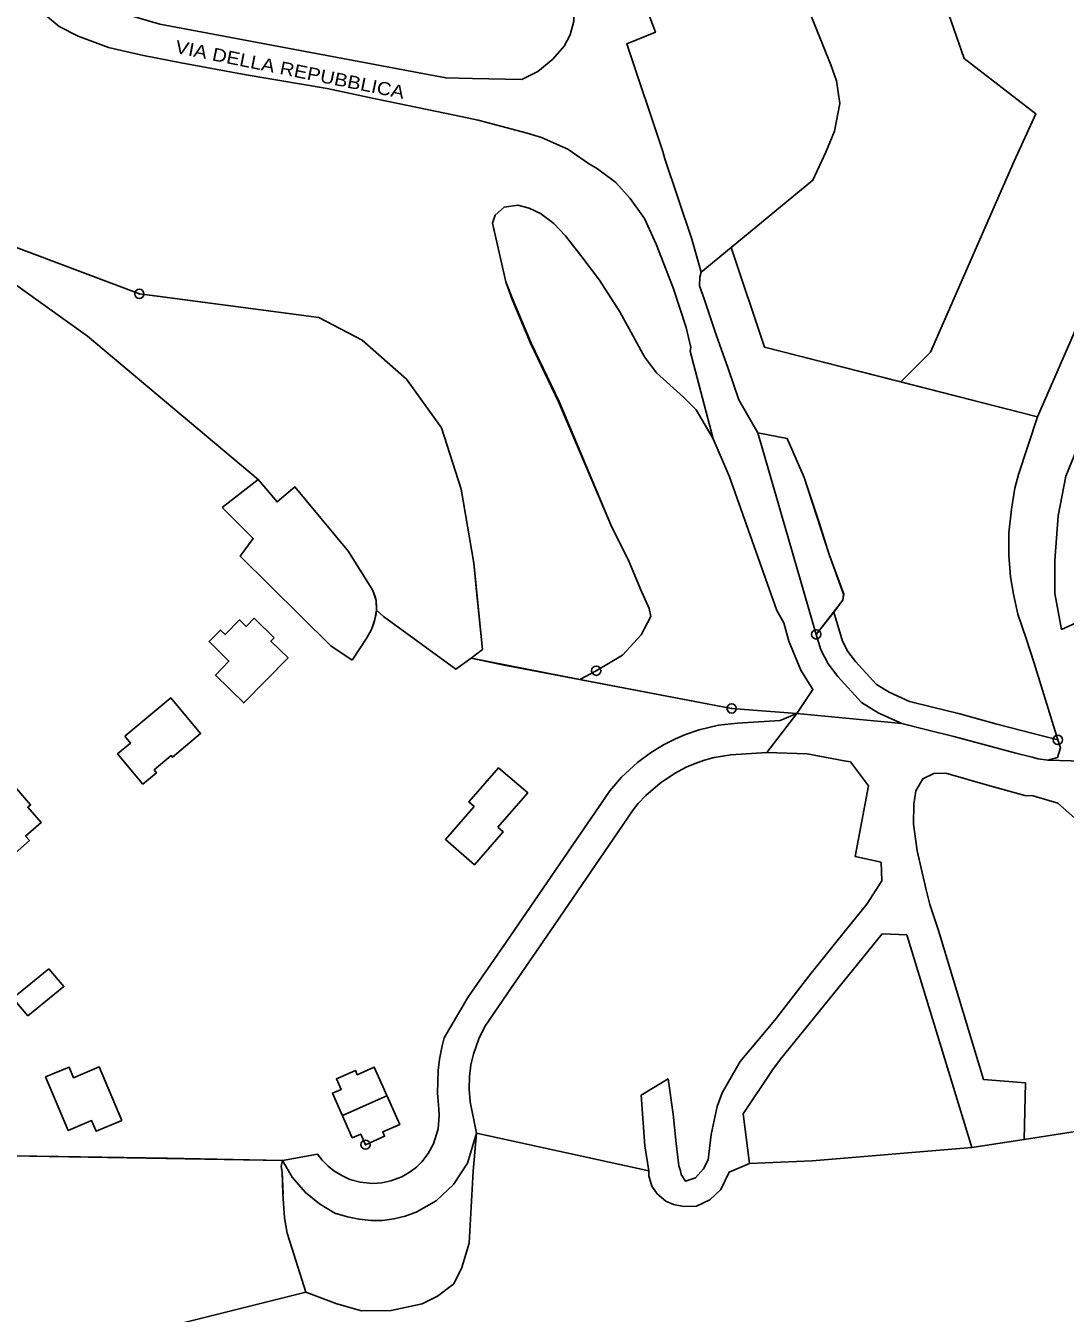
# Model space of a CAD drawing. Extents: x 654952 to 658955, y 890426 to 894481.
# Drawn here: x 657405.1 to 657629.2, y 891411.2 to 891688.7 of the extents above; entities that cross this region are included whole.
import ezdxf

# ---------------------------------------------------------------- set-up
doc = ezdxf.new("R2010")
doc.units = 0
doc.header["$LTSCALE"] = 4
doc.header["$PDMODE"] = 32
doc.header["$PDSIZE"] = 2
for name, color, linetype, lineweight in [('11', 7, 'Continuous', 25), ('14', 7, 'Continuous', 25), ('17', 7, 'Continuous', 25), ('18', 7, 'Continuous', 25), ('19', 7, 'Continuous', 25), ('32', 7, 'Continuous', 25), ('33', 7, 'Continuous', 25), ('5', 7, 'Continuous', 25), ('6', 7, 'Continuous', 25), ('9', 7, 'Continuous', 25)]:
    doc.layers.add(name, color=color, linetype=linetype, lineweight=lineweight)
doc.layers.add('58', color=7, linetype='Continuous')

msp = doc.modelspace()

# ---------------------------------------------------------------- linework, layer by layer
at = {"layer": '11'}
for points in [[(657536.04, 891519.7), (657537.15, 891521.09), (657538.76, 891522.8), (657541.9, 891525.5), (657544.99, 891527.57), (657547.51, 891528.89), (657549.45, 891529.72), (657551.45, 891530.43), (657553.5, 891531), (657557.09, 891531.61), (657564.89, 891532.09), (657573.54, 891531.8), (657581.52, 891530.26), (657582.89, 891530.1), (657586.75, 891524.92), (657583.92, 891509.65), (657589.53, 891508.48)], [(657612.44, 891525.06), (657603.45, 891527.64), (657600.85, 891527.58), (657598.53, 891526.44), (657597.01, 891523.81), (657596.57, 891520.94), (657596.5, 891516.66), (657597.25, 891510.92), (657599.18, 891502.46), (657600, 891499.29), (657601.87, 891493.71), (657611.58, 891461.59), (657620.6, 891460.91), (657620.37, 891448.67), (657651.61, 891453.59), (657647.29, 891466.67), (657646.69, 891468.3), (657639.1, 891492.2), (657638.77, 891494.29)], [(657638.77, 891494.29), (657635.87, 891502.88), (657631.27, 891517.96), (657627.62, 891521.13), (657622.31, 891522.75), (657620.45, 891522.84), (657612.44, 891525.06)], [(657502.32, 891450.02), (657500.91, 891456.77), (657500.69, 891459.53), (657500.77, 891462.22), (657501.09, 891464.75), (657501.61, 891467.08), (657502.76, 891470.34), (657504.09, 891473.02), (657509.87, 891481.47), (657518.23, 891493.68), (657532.81, 891514.99), (657536.04, 891519.7)], [(657589.53, 891508.48), (657589.69, 891504.43), (657586.45, 891499.36), (657581.8, 891493.72), (657574.45, 891484.53), (657566.61, 891474.36), (657559.15, 891465.47), (657555.22, 891458.75), (657554.15, 891455.81), (657552.85, 891449.75), (657552.25, 891444.26), (657551.19, 891442.34), (657549.5, 891440.43), (657547.35, 891439.69), (657546.44, 891441.15), (657546.23, 891441.94), (657545.89, 891443.03), (657545.32, 891447.82), (657544.66, 891454.16), (657543.59, 891461.72), (657537.79, 891458.26), (657538.56, 891447.28), (657539.42, 891441.94), (657502.32, 891450.02)]]:
    msp.add_lwpolyline(points, dxfattribs=at)
msp.add_lwpolyline([(657567.81, 891465.96), (657589.76, 891493), (657595.02, 891492.76), (657609.06, 891446.97), (657574.67, 891444.05), (657561.12, 891443.52), (657559.77, 891454.2), (657566.15, 891463.76)], close=True, dxfattribs=at)
at = {"layer": '14'}
for points in [[(657571.63, 891697.78), (657578.7, 891680.26), (657579.86, 891676.86), (657580.58, 891671.95), (657579.45, 891666.01), (657577.58, 891661.44), (657574.82, 891655.41), (657557.15, 891640.89), (657564.35, 891619.47), (657593.79, 891611.94), (657600.13, 891618.34), (657618.17, 891659.54), (657622.86, 891669.7), (657607.43, 891681.63), (657589.08, 891734.34)], [(657557.28, 891541.57), (657524.55, 891547.8), (657528.1, 891549.71), (657533.76, 891553.06), (657537.8, 891557.41), (657539.84, 891561.4), (657539.53, 891563.14), (657537.66, 891567.25), (657534.97, 891573.65), (657531.49, 891580.63), (657519.98, 891607.69), (657513.95, 891620.31), (657510.01, 891629.68), (657508.61, 891633.49), (657505.74, 891646.17), (657506.32, 891647.92), (657508.22, 891649.62), (657511.18, 891650.01), (657513.67, 891649.41), (657516.12, 891648.27), (657518.95, 891646.06), (657521.49, 891643.41), (657524.99, 891638.94), (657528.77, 891633.84), (657533.18, 891627.04), (657538.49, 891617.32), (657541.06, 891613.9)], [(657541.06, 891613.9), (657546.91, 891608.63), (657549.64, 891605.93), (657553.31, 891599.66), (657556.8, 891591.46), (657567.02, 891562.66)], [(657567.02, 891562.66), (657568.57, 891560.05), (657569.63, 891556.08), (657572.23, 891549.79), (657574.79, 891545.67), (657571.32, 891540.46), (657557.28, 891541.57)]]:
    msp.add_lwpolyline(points, dxfattribs=at)
msp.add_point((657557.28, 891541.57), dxfattribs=at)
at = {"layer": '17'}
for points in [[(657651.61, 891453.59), (657620.37, 891448.67), (657609.06, 891446.97), (657574.67, 891444.05), (657561.12, 891443.52), (657556.76, 891441.67), (657554.92, 891437.87), (657552.58, 891435.65), (657549.7, 891434.31), (657546.97, 891434.25), (657544.74, 891434.69), (657543.13, 891435.39), (657541.21, 891436.96), (657540.11, 891438.59), (657539.43, 891440.88), (657539.42, 891441.94), (657502.32, 891450.02)], [(657502.32, 891450.02), (657501.58, 891441.87), (657500.7, 891426.32), (657499.1, 891421.08), (657497.41, 891417.57), (657493.9, 891414.91), (657490.61, 891413.25), (657483.89, 891411.8), (657477.48, 891411.73), (657472.18, 891413.29), (657465.47, 891415.8), (657379.19, 891394.2)], [(657472.18, 891413.29), (657477.48, 891411.73), (657483.89, 891411.8), (657490.61, 891413.25), (657493.9, 891414.91), (657497.41, 891417.57), (657499.1, 891421.08), (657500.7, 891426.32), (657501.58, 891441.87), (657502.32, 891450.02), (657500.34, 891443.59), (657497.35, 891438.99)], [(657471.75, 891432.78), (657468.43, 891434.83), (657465.43, 891437.22), (657462.57, 891440.53), (657460.49, 891444.17), (657460.21, 891442.85), (657460.39, 891441.67), (657460.59, 891437)], [(657497.35, 891438.99), (657493.63, 891435.44), (657489.29, 891433), (657486.95, 891432.14), (657484.5, 891431.55), (657482.05, 891431.25), (657479.55, 891431.22), (657476.99, 891431.48), (657474.51, 891432.04), (657471.75, 891432.78)], [(657460.58, 891437), (657460.88, 891431.76), (657461.51, 891428.49), (657462.51, 891425.34), (657465.47, 891415.8), (657472.18, 891413.29)]]:
    msp.add_lwpolyline(points, dxfattribs=at)
at = {"layer": '18'}
for points in [[(657575.52, 891557.54), (657581.28, 891564.88), (657581.44, 891566.22), (657578.28, 891574.76), (657576.12, 891581.63), (657572.92, 891591.37), (657569.26, 891599.75), (657562.94, 891600.94)], [(657410.14, 891485.45), (657402.37, 891479.15), (657405.6, 891475.33), (657413.37, 891481.63)]]:
    msp.add_lwpolyline(points, close=True, dxfattribs=at)
for points in [[(657474.7, 891575.38), (657463.15, 891589.31), (657459.31, 891586.11), (657455.2, 891590.93), (657447.48, 891584.85)], [(657447.48, 891584.85), (657454.18, 891578.21), (657451.35, 891574.36), (657470.88, 891555.09), (657475.47, 891552.01)], [(657475.47, 891552.01), (657478.66, 891556.78), (657479.64, 891558.61), (657480.41, 891560.73), (657480.75, 891562.79), (657480.66, 891564.82), (657479.94, 891566.96), (657474.7, 891575.38)]]:
    msp.add_lwpolyline(points, dxfattribs=at)
msp.add_point((657575.52, 891557.54), dxfattribs=at)
at = {"layer": '19'}
for points in [[(657627.6, 891534.79), (657628.17, 891533.07), (657627.52, 891531), (657625.45, 891530.42), (657623.33, 891530.7), (657622.04, 891531.05), (657618.56, 891531.96), (657613.2, 891533.35), (657605.18, 891535.54), (657599.1, 891537.05), (657593.99, 891538.35), (657588.86, 891540.64), (657585.28, 891542.87), (657580.15, 891548.47), (657578.1, 891551.16), (657576.5, 891554.19), (657575.51, 891557.54), (657579.3, 891562.36)], [(657579.3, 891562.36), (657581.15, 891556.08), (657582.33, 891553.86), (657583.99, 891551.68), (657588.5, 891546.75), (657591.21, 891545.07), (657595.64, 891543.09), (657600.32, 891541.9), (657606.44, 891540.38), (657614.48, 891538.18), (657627.6, 891534.79)]]:
    msp.add_lwpolyline(points, dxfattribs=at)
msp.add_point((657627.6, 891534.79), dxfattribs=at)
at = {"layer": '32'}
msp.add_lwpolyline([(657379.19, 891394.2), (657465.47, 891415.8), (657462.51, 891425.34), (657461.51, 891428.49), (657460.88, 891431.76), (657460.58, 891437), (657460.39, 891441.67), (657460.21, 891442.85), (657460.49, 891444.17), (657393.37, 891445.28)], dxfattribs=at)
at = {"layer": '33'}
msp.add_line((657500.41, 891479.3), (657495.33, 891470.58), dxfattribs=at)
for points in [[(657435.67, 891444.62), (657393.37, 891445.28), (657394.07, 891435.22), (657386.64, 891435.1), (657369.3, 891520.67), (657309.08, 891592.79), (657241.81, 891673.31)], [(657400.23, 891642.01), (657429.62, 891630.91), (657468.34, 891625.81), (657477.62, 891620.95), (657487.17, 891612.52), (657494.75, 891602.06), (657498.97, 891588.85), (657501.72, 891572.87), (657503.56, 891554.3), (657501.11, 891552.38), (657497.87, 891550.01), (657482.22, 891561.42), (657480.75, 891562.79), (657480.77, 891563.22), (657480.67, 891564.82), (657480.48, 891565.65), (657479.95, 891566.96), (657474.7, 891575.38), (657463.15, 891589.31), (657459.31, 891586.1), (657455.2, 891590.93), (657418.41, 891621.84), (657394.81, 891638.71)], [(657394.8, 891638.71), (657418.41, 891621.84), (657455.2, 891590.93), (657447.48, 891584.85)], [(657447.48, 891584.85), (657454.18, 891578.21), (657451.35, 891574.36), (657470.88, 891555.09), (657475.47, 891552.01)], [(657475.47, 891552.01), (657478.66, 891556.78), (657479.64, 891558.61), (657480.1, 891559.73), (657480.41, 891560.73), (657480.65, 891561.88), (657480.75, 891562.79), (657482.21, 891561.42)], [(657482.21, 891561.42), (657497.87, 891550.01), (657501.11, 891552.39), (657507.92, 891550.96), (657557.28, 891541.57), (657571.32, 891540.46), (657567.75, 891538.97), (657558.52, 891538.43), (657554.45, 891537.94), (657550.29, 891536.98), (657547.37, 891535.96), (657545.17, 891535.03), (657542.63, 891533.75), (657539.8, 891532.02), (657537.02, 891529.96), (657533.53, 891526.74), (657531, 891523.8), (657527.93, 891519.3)], [(657571.32, 891540.46), (657567.75, 891538.97), (657558.52, 891538.43), (657554.45, 891537.94), (657550.29, 891536.98), (657547.37, 891535.96), (657545.17, 891535.03), (657542.63, 891533.75), (657539.8, 891532.02), (657537.02, 891529.96), (657533.53, 891526.74), (657531, 891523.8), (657527.93, 891519.3)], [(657551.45, 891530.43), (657553.5, 891531), (657557.09, 891531.61), (657564.89, 891532.09), (657571.32, 891540.46)], [(657536.04, 891519.7), (657537.15, 891521.09), (657538.76, 891522.8), (657541.9, 891525.5), (657544.99, 891527.57), (657547.51, 891528.89), (657549.45, 891529.72), (657551.45, 891530.43)], [(657527.93, 891519.3), (657522.92, 891511.95), (657515.7, 891501.47), (657508.67, 891491.24), (657500.41, 891479.3), (657495.33, 891470.58)], [(657527.93, 891519.3), (657522.92, 891511.95), (657515.7, 891501.47), (657508.67, 891491.24), (657500.41, 891479.3)], [(657502.32, 891450.02), (657500.91, 891456.77), (657500.69, 891459.53), (657500.77, 891462.22), (657501.09, 891464.75), (657501.61, 891467.08), (657502.76, 891470.34), (657504.09, 891473.02), (657509.87, 891481.47), (657518.23, 891493.68), (657532.81, 891514.99), (657536.04, 891519.7)], [(657495.33, 891470.58), (657494.89, 891468.89), (657494.32, 891465.96), (657494.01, 891463.53), (657493.88, 891458.65), (657494.16, 891455.21), (657494.26, 891453.87), (657494.04, 891451.01), (657493.05, 891447.75), (657491.9, 891445.64), (657490.54, 891443.88), (657489.33, 891442.7), (657488.01, 891441.68), (657486.22, 891440.64), (657483.85, 891439.74), (657481.85, 891439.32), (657479.87, 891439.19), (657477.23, 891439.45), (657475.01, 891440.07), (657473.24, 891440.91)], [(657495.33, 891470.58), (657494.89, 891468.89), (657494.32, 891465.96), (657494.01, 891463.53), (657493.88, 891458.65), (657494.16, 891455.21), (657494.26, 891453.87), (657494.04, 891451.01), (657493.05, 891447.75), (657491.9, 891445.64), (657490.54, 891443.88), (657489.33, 891442.7), (657488.01, 891441.68), (657486.22, 891440.64), (657483.85, 891439.74), (657481.85, 891439.32), (657479.87, 891439.19), (657477.23, 891439.45), (657475.01, 891440.07), (657473.24, 891440.91)], [(657465.43, 891437.22), (657468.43, 891434.83), (657471.75, 891432.78), (657474.51, 891432.04), (657476.99, 891431.48), (657479.55, 891431.22), (657482.05, 891431.25), (657484.5, 891431.55), (657486.95, 891432.14), (657489.29, 891433), (657493.63, 891435.44), (657497.35, 891438.99), (657500.34, 891443.59), (657502.32, 891450.02)], [(657473.24, 891440.91), (657471.51, 891441.93), (657470.31, 891442.91), (657469.03, 891444.24), (657468.04, 891445.54), (657460.49, 891444.17), (657435.67, 891444.62)], [(657473.24, 891440.91), (657471.51, 891441.93), (657470.31, 891442.91), (657469.03, 891444.24), (657468.04, 891445.54), (657460.49, 891444.17), (657462.57, 891440.53), (657465.43, 891437.22)]]:
    msp.add_lwpolyline(points, dxfattribs=at)
at = {"layer": '5'}
for p, q in [((657575.52, 891557.54), (657562.94, 891600.94)), ((657571.32, 891540.46), (657593.99, 891538.35))]:
    msp.add_line(p, q, dxfattribs=at)
for points in [[(657493.05, 891718.92), (657495.32, 891719.49), (657496.49, 891719.4), (657505.82, 891717.61), (657509.57, 891716.5), (657512.54, 891714.77), (657515.53, 891712.53), (657518.22, 891709.64), (657520.12, 891706.27), (657521.62, 891702.13), (657522.77, 891697.46), (657523.2, 891694.06), (657523.25, 891689.69), (657522.48, 891686.72), (657521.17, 891684.28), (657518.74, 891681.53), (657515.54, 891678.84), (657512.03, 891677.11), (657501.45, 891677.37), (657495.69, 891677.51), (657434, 891689.06), (657424.67, 891691.78)], [(657562.94, 891600.94), (657558.81, 891608.09), (657556.51, 891614.85), (657553.98, 891622.1), (657551.38, 891629.84), (657550.35, 891632.65), (657550.4, 891634.52), (657550.74, 891635.6), (657548.69, 891642.72), (657542.89, 891660), (657542.44, 891661.57), (657534.68, 891684.82), (657540.84, 891687.29), (657531.06, 891713.58), (657529.05, 891712.8), (657527.09, 891711.76)], [(657405.83, 891693.98), (657412.36, 891688.52), (657416.42, 891686.48), (657420.67, 891684.85), (657422.95, 891684.04), (657426.72, 891683.18), (657430.49, 891682.32), (657438.63, 891680.71)], [(657658.46, 891692.53), (657658.79, 891689.12), (657657.69, 891683.67), (657656.58, 891678.97), (657655.66, 891675.31), (657653.6, 891669.86), (657650.32, 891662.32), (657648.79, 891661.73), (657644.82, 891652.84), (657634.79, 891630.7), (657632.64, 891625.95), (657623.23, 891604.4), (657619.09, 891592)], [(657438.63, 891680.71), (657452.65, 891678.12), (657470.09, 891675.16), (657479.12, 891673.26), (657497.53, 891669.47), (657502.67, 891668.35), (657507.54, 891667.04), (657513.19, 891665.59), (657516.32, 891664.61), (657521.95, 891662.11), (657526.46, 891659)], [(657526.46, 891659), (657528.37, 891657.87), (657532.3, 891654.92), (657535.38, 891651.46), (657538.48, 891647.19), (657541.03, 891641.6), (657544.68, 891632.2), (657547.46, 891623.7), (657548.49, 891619.33), (657548.37, 891618.6), (657553.31, 891599.66), (657556.8, 891591.46), (657567.02, 891562.66)], [(657627.6, 891534.79), (657628.17, 891533.07), (657627.52, 891531), (657625.45, 891530.42), (657645.47, 891529.84), (657645.56, 891536.63), (657633.9, 891561.11), (657628.36, 891558.61), (657626.93, 891566.36), (657626.93, 891573.49), (657627.68, 891583.11), (657629.3, 891591.67), (657631.12, 891596.05), (657640, 891619.78), (657641.69, 891619.02), (657654.9, 891646.35)], [(657619.09, 891592), (657618.35, 891589.03), (657617.59, 891584.52), (657617.04, 891579.4), (657617, 891574.63), (657617.36, 891569.93), (657618.03, 891566.21), (657618.95, 891561.92), (657620.74, 891556.63), (657622.5, 891551.32), (657627.6, 891534.79)], [(657567.02, 891562.66), (657568.57, 891560.05), (657569.63, 891556.08), (657572.23, 891549.79), (657574.79, 891545.67), (657571.32, 891540.46), (657593.99, 891538.35)], [(657593.99, 891538.35), (657588.86, 891540.64), (657585.28, 891542.87), (657580.15, 891548.47), (657578.1, 891551.16), (657576.5, 891554.19), (657575.51, 891557.54)], [(657625.45, 891530.42), (657623.33, 891530.7), (657622.04, 891531.05), (657618.56, 891531.96), (657613.2, 891533.35), (657605.18, 891535.54), (657599.1, 891537.05), (657593.99, 891538.35), (657571.32, 891540.46), (657564.89, 891532.09)], [(657564.89, 891532.09), (657573.54, 891531.8), (657581.52, 891530.26), (657582.89, 891530.1), (657586.75, 891524.92), (657583.92, 891509.65), (657589.53, 891508.48)], [(657658, 891467.15), (657647.42, 891500.81), (657640.71, 891522.01), (657645.47, 891529.84), (657625.45, 891530.42)], [(657600, 891499.29), (657599.18, 891502.46), (657597.25, 891510.92), (657596.5, 891516.66), (657596.57, 891520.94), (657597.01, 891523.81), (657598.53, 891526.44), (657600.85, 891527.58), (657603.45, 891527.64), (657612.44, 891525.06), (657620.45, 891522.84)], [(657620.45, 891522.84), (657622.31, 891522.75), (657627.62, 891521.13), (657631.27, 891517.96), (657635.87, 891502.88), (657638.77, 891494.29), (657639.1, 891492.2), (657646.69, 891468.3), (657647.29, 891466.67), (657651.61, 891453.59), (657654.91, 891446.58)], [(657589.53, 891508.48), (657589.69, 891504.43), (657586.45, 891499.36), (657581.8, 891493.72), (657574.45, 891484.53), (657566.61, 891474.36), (657559.15, 891465.47), (657555.22, 891458.75), (657554.15, 891455.81), (657552.85, 891449.75), (657552.25, 891444.26), (657551.19, 891442.34), (657549.5, 891440.43), (657547.35, 891439.69), (657546.44, 891441.15), (657546.23, 891441.94), (657545.89, 891443.03), (657545.32, 891447.82), (657544.66, 891454.16), (657543.59, 891461.72), (657537.79, 891458.26), (657538.56, 891447.28), (657539.42, 891441.94), (657539.43, 891440.88), (657540.11, 891438.59), (657541.21, 891436.96), (657543.13, 891435.39), (657544.74, 891434.69), (657546.97, 891434.25), (657549.7, 891434.31), (657552.58, 891435.65), (657554.92, 891437.87), (657556.76, 891441.67), (657561.12, 891443.52), (657559.77, 891454.2), (657566.15, 891463.76), (657567.81, 891465.96), (657589.76, 891493), (657595.02, 891492.76), (657609.06, 891446.97)], [(657609.06, 891446.97), (657620.37, 891448.67), (657620.6, 891460.91), (657611.58, 891461.59), (657601.87, 891493.71), (657600, 891499.29)]]:
    msp.add_lwpolyline(points, dxfattribs=at)
at = {"layer": '6'}
msp.add_line((657473.39, 891453.84), (657482.99, 891458.1), dxfattribs=at)
for points in [[(657458.65, 891556.81), (657454.37, 891561.02), (657452.62, 891559.23), (657451.2, 891560.64), (657448.11, 891557.5), (657447.11, 891558.48), (657444.66, 891555.98), (657448.94, 891551.78), (657446, 891548.78), (657452.13, 891542.75), (657461.66, 891552.45), (657457.95, 891556.1)], [(657426.49, 891535.57), (657436.39, 891543.84), (657442.8, 891536.16), (657436.73, 891531.1), (657436.48, 891531.41), (657432.79, 891528.33), (657433.3, 891527.72), (657430.38, 891525.28), (657424.94, 891531.81), (657427.7, 891534.11)], [(657409.4, 891462.15), (657414.26, 891450.63), (657419.33, 891452.77), (657420.3, 891450.47), (657425.83, 891452.8), (657420.97, 891464.32), (657415.44, 891461.98), (657414.47, 891464.29)], [(657478.36, 891447.56), (657477.35, 891449.85), (657475.52, 891449.04), (657471.26, 891458.64), (657473.09, 891459.45), (657472.08, 891461.73), (657476.19, 891463.56), (657476.6, 891462.64), (657480.25, 891464.27), (657485.73, 891451.93), (657482.07, 891450.3), (657482.48, 891449.39)]]:
    msp.add_lwpolyline(points, close=True, dxfattribs=at)
for points in [[(657501.76, 891520.44), (657500.63, 891521.42), (657507.06, 891528.81), (657513.32, 891523.36), (657506.89, 891515.97)], [(657405.96, 891513.08), (657405.09, 891514.08), (657408.42, 891516.96), (657405.56, 891520.27), (657406.16, 891520.79), (657402.24, 891525.33)], [(657506.89, 891515.97), (657508.02, 891514.99), (657501.84, 891507.9), (657495.58, 891513.35), (657501.76, 891520.44)], [(657392.19, 891517.68), (657397.16, 891511.94), (657397.76, 891512.46), (657400.97, 891508.76), (657405.96, 891513.08)]]:
    msp.add_lwpolyline(points, dxfattribs=at)
msp.add_point((657478.36, 891447.56), dxfattribs=at)
at = {"layer": '9'}
msp.add_line((657528.1, 891549.71), (657524.55, 891547.8), dxfattribs=at)
for points in [[(657578.61, 891784.11), (657582.17, 891781.28), (657584.94, 891779.5), (657587.7, 891777.72), (657597.04, 891775.75), (657593.2, 891771.15), (657589.35, 891766.55), (657583.84, 891761.75), (657581.13, 891753.01), (657589.08, 891734.34), (657607.43, 891681.63), (657622.86, 891669.7), (657618.17, 891659.54), (657600.13, 891618.34), (657593.79, 891611.94), (657623.23, 891604.4)], [(657409.21, 891719.99), (657408.32, 891715.99), (657408.22, 891712.03), (657408.92, 891708.47), (657410.21, 891704.31), (657411.99, 891701.34), (657414.04, 891698.48), (657416.55, 891696.07), (657420.03, 891693.69), (657422.69, 891692.44), (657424.67, 891691.78), (657434, 891689.06), (657495.69, 891677.51), (657501.45, 891677.37)], [(657501.45, 891677.37), (657512.03, 891677.11), (657515.54, 891678.84), (657518.74, 891681.53), (657521.17, 891684.28), (657522.48, 891686.72), (657523.25, 891689.69), (657523.2, 891694.06), (657522.77, 891697.46), (657521.62, 891702.13), (657520.12, 891706.27), (657518.22, 891709.64), (657515.53, 891712.53), (657512.54, 891714.77), (657509.57, 891716.5), (657505.82, 891717.61), (657496.49, 891719.4), (657495.32, 891719.49), (657493.05, 891718.92)], [(657405.83, 891693.98), (657412.36, 891688.52), (657416.42, 891686.48), (657420.67, 891684.85), (657422.95, 891684.04), (657426.72, 891683.18), (657430.49, 891682.32), (657438.63, 891680.71), (657452.65, 891678.12), (657470.09, 891675.16), (657479.12, 891673.26)], [(657429.62, 891630.91), (657400.23, 891642.01), (657363.97, 891674.93)], [(657479.12, 891673.26), (657497.53, 891669.47), (657502.67, 891668.35), (657507.54, 891667.04), (657513.19, 891665.59), (657516.32, 891664.61), (657521.95, 891662.11), (657526.46, 891659)], [(657623.23, 891604.4), (657632.64, 891625.95), (657634.79, 891630.7), (657644.82, 891652.84), (657648.79, 891661.73)], [(657526.46, 891659), (657528.37, 891657.87), (657532.3, 891654.92), (657535.38, 891651.46), (657538.48, 891647.19), (657541.03, 891641.6), (657544.68, 891632.2), (657547.46, 891623.7), (657548.49, 891619.33), (657548.37, 891618.6), (657553.31, 891599.66), (657549.64, 891605.93), (657546.91, 891608.63), (657541.06, 891613.9), (657538.49, 891617.32), (657533.18, 891627.04), (657528.77, 891633.84), (657524.99, 891638.94), (657521.49, 891643.41), (657518.95, 891646.06), (657516.12, 891648.27), (657513.67, 891649.41), (657511.18, 891650.01), (657508.22, 891649.62), (657506.32, 891647.92), (657505.74, 891646.17), (657508.61, 891633.49), (657510.13, 891629.69), (657514.07, 891620.32), (657520.1, 891607.7), (657531.49, 891580.63), (657534.97, 891573.65), (657537.66, 891567.25), (657539.53, 891563.14), (657539.84, 891561.4), (657537.8, 891557.41), (657533.76, 891553.06), (657528.1, 891549.71)], [(657562.94, 891600.94), (657558.81, 891608.09), (657556.51, 891614.85), (657553.98, 891622.1), (657551.38, 891629.84), (657550.35, 891632.65), (657550.4, 891634.52), (657550.74, 891635.6), (657557.15, 891640.89), (657564.35, 891619.47), (657623.23, 891604.4), (657619.09, 891592)], [(657524.55, 891547.8), (657501.11, 891552.39), (657503.55, 891554.3), (657502.31, 891566.84), (657501.72, 891572.87), (657498.97, 891588.85), (657494.75, 891602.06), (657487.17, 891612.52), (657477.62, 891620.95), (657468.34, 891625.81), (657433.51, 891630.4), (657429.62, 891630.91)], [(657626.93, 891573.49), (657627.68, 891583.11), (657629.3, 891591.67), (657631.12, 891596.05), (657640, 891619.78), (657671.35, 891605.74), (657689.24, 891586.11)], [(657627.6, 891534.79), (657614.48, 891538.18), (657606.44, 891540.38), (657600.32, 891541.9), (657595.64, 891543.09), (657591.21, 891545.07), (657588.5, 891546.75), (657583.99, 891551.68), (657582.33, 891553.86), (657581.15, 891556.08), (657579.3, 891562.36), (657581.28, 891564.88), (657581.43, 891566.22), (657578.28, 891574.76), (657572.92, 891591.37), (657569.26, 891599.75), (657562.94, 891600.94)], [(657619.09, 891592), (657618.35, 891589.03), (657617.59, 891584.52), (657617.04, 891579.4), (657617, 891574.63), (657617.36, 891569.93), (657618.03, 891566.21), (657618.95, 891561.92), (657620.74, 891556.63), (657622.5, 891551.32), (657627.6, 891534.79)], [(657689.24, 891586.11), (657682.3, 891570.49), (657684.55, 891562.67), (657730.99, 891539.3), (657734.55, 891533.67), (657744.04, 891518.8), (657738.12, 891505.34), (657727.6, 891493.76), (657723.06, 891499.45), (657675.43, 891520.8), (657666.96, 891524.08), (657645.47, 891529.84), (657645.56, 891536.63), (657633.9, 891561.11), (657628.36, 891558.61), (657626.93, 891566.36), (657626.93, 891573.49)]]:
    msp.add_lwpolyline(points, dxfattribs=at)
msp.add_lwpolyline([(657534.68, 891684.82), (657542.44, 891661.57), (657542.89, 891660), (657548.69, 891642.72), (657550.74, 891635.6), (657557.15, 891640.89), (657574.82, 891655.41), (657577.58, 891661.44), (657579.45, 891666.01), (657580.58, 891671.95), (657579.86, 891676.86), (657578.7, 891680.26), (657571.63, 891697.78), (657558.49, 891728.67), (657558.5, 891730.13), (657555.63, 891737.11), (657553.52, 891737.12), (657539.55, 891731.48), (657540.24, 891729.21), (657535.01, 891727.06), (657539.24, 891716.78), (657531.06, 891713.58), (657540.84, 891687.29)], close=True, dxfattribs=at)
for p in [(657429.62, 891630.91), (657528.1, 891549.71)]:
    msp.add_point(p, dxfattribs=at)

# ---------------------------------------------------------------- texts
at = {"layer": '58', "width": 1.15}
msp.add_text('VIA DELLA REPUBBLICA', height=2.802, rotation=348.58, dxfattribs=at).set_placement((657437.16, 891682.89))

doc.saveas('drawing.dxf')
